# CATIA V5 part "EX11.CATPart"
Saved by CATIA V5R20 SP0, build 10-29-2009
Part number: EX11
Bounding box of the stored display mesh (mm): x -11.99 to 130.452, y 0 to 96.181, z 0 to 10
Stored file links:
  E:\Nouveau dossier\tarek\mécaniquee\Catia\TP 0\EX11.CATPart
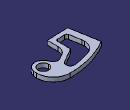
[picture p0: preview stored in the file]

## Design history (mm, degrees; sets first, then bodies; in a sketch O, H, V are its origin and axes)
Set1
  DatumSurface1 to DatumSurface23
Body1 (main body)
